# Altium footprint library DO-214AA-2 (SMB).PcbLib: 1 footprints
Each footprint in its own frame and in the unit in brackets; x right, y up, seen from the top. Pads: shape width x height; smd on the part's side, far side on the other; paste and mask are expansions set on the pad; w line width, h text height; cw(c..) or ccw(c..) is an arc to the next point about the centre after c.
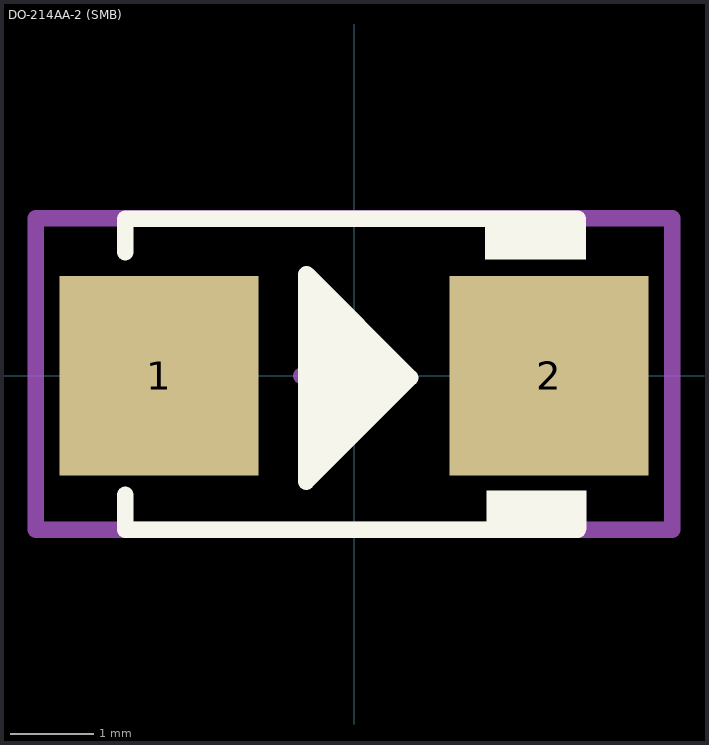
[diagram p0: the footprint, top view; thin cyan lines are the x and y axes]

## DO-214AA-2 (SMB) [mm] "5.6mm x 3.95mm"
height 2.45
pads (2):
  rect 2.4x2.4 smd: 1(-2.35,0) 2(2.35,0)
Top Overlay:
  rectangle: 1.58,1.402 2.796,1.877
  rectangle: 1.597,-1.858 2.8,-1.382
  region: -0.577,1.22 -0.577,-1.279 0.677,-0.025 0.677,-0.024
  lines w0.2: -2.756,-1.434 -2.756,-1.858 2.699,-1.858 ; -2.756,1.488 -2.756,1.893 2.698,1.893 ; -0.577,-1.279 0.677,-0.025 -0.569,1.22 -0.577,1.22 -0.577,-1.279
Mechanical 15:
  lines w0.2: -0.635,0 0.635,0 ; 0,-0.635 0,0.635 ; -3.835,-1.858 3.835,-1.858 3.835,1.899 2.899,1.899 -3.835,1.899 -3.835,-1.858
3D body "DO-214AA.stp": height 2.65, standoff 0, extent -2.8,-1.956 2.8,1.994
